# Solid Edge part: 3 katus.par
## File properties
Author: Henri
Template: Normal.par
Last saved by: Henri
Revision: 24
Application: Solid Edge
Accuracy: 0,990
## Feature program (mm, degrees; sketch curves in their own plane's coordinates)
sketch for "unnamed Protrusion 1" plane through (0, 0, 0) normal (0, 0, 1) x-axis (1, 0, 0)
  line (-137.5, -225) -> (-137.5, 225)
  line (-137.5, 225) -> (137.5, 225)
  line (137.5, 225) -> (137.5, -225)
  line (137.5, -225) -> (-137.5, -225)
extrude "unnamed Protrusion 1" add finite 5 along -normal
sketch for "ExtrudedProtrusion_4" plane through (0, 0, 0) normal (0, 0, 1) x-axis (1, 0, 0)
  line (137.5, -230) -> (-207.5, -230)
  line (-212.5, -225) -> (-207.5, -230)
  line (-212.5, 225) -> (-212.5, -225)
  line (-207.5, 230) -> (-212.5, 225)
  line (-207.5, 230) -> (137.5, 230)
  line (142.5, 225) -> (137.5, 230)
  line (142.5, 225) -> (142.5, -225)
  line (137.5, -230) -> (142.5, -225)
extrude "ExtrudedProtrusion_4" add finite 5 along +normal
chamfer "Chamfer_4" setback 5
sketch for "ExtrudedProtrusion_42" plane through (-35, 0, 5) normal (0, 0, 1) x-axis (0, 1, 0)
  circle centre (-220, 167.5) radius 1.25
extrude "ExtrudedProtrusion_42" add finite 40 along +normal
sketch for "ExtrudedProtrusion_43" plane through (-35, 0, 5) normal (0, 0, 1) x-axis (0, 1, 0)
  circle centre (220, 167.5) radius 1.25
extrude "ExtrudedProtrusion_43" add finite 40 along +normal
sketch for "ExtrudedProtrusion_44" plane through (-35, 0, 5) normal (0, 0, 1) x-axis (0, 1, 0)
  circle centre (-220, -167.5) radius 1.25
extrude "ExtrudedProtrusion_44" add finite 40 along +normal
pattern "Pattern_9" of "ExtrudedProtrusion_42" along a curve  XDirCount = 5; XDirSpacing = 55 mm
extrude "unnamed Protrusion 2" add finite 40
extrude "unnamed Protrusion 3" add finite 40
extrude "unnamed Protrusion 4" add finite 40
extrude "unnamed Protrusion 5" add finite 40
extrude "unnamed Protrusion 6" add finite 40
extrude "unnamed Protrusion 7" add finite 40
extrude "unnamed Protrusion 8" add finite 40
pattern "Pattern_12" of "ExtrudedProtrusion_43" along a curve  XDirCount = 6; XDirSpacing = 67 mm
extrude "unnamed Protrusion 9" add finite 40
extrude "unnamed Protrusion 10" add finite 40
extrude "unnamed Protrusion 11" add finite 40
extrude "unnamed Protrusion 12" add finite 40
extrude "unnamed Protrusion 13" add finite 40
pattern "Pattern_13" of "ExtrudedProtrusion_44" along a curve  XDirCount = 6; XDirSpacing = 55 mm
extrude "unnamed Protrusion 14" add finite 40
extrude "unnamed Protrusion 15" add finite 40
extrude "unnamed Protrusion 16" add finite 40
extrude "unnamed Protrusion 17" add finite 40
extrude "unnamed Protrusion 18" add finite 40
extrude "unnamed Protrusion 19" add finite 40
extrude "unnamed Protrusion 20" add finite 40
pattern "Pattern_14" of "ExtrudedProtrusion_42" along a curve  XDirCount = 5; XDirSpacing = 67 mm
extrude "unnamed Protrusion 21" add finite 40
extrude "unnamed Protrusion 22" add finite 40
extrude "unnamed Protrusion 23" add finite 40
extrude "unnamed Protrusion 24" add finite 40
swept protrusion "unnamed SweptProtrusion 1"
fillet "Round_7" radius 1
sketch used by "unnamed Cutout 1" plane through (-35, 0, 5) normal (0, 0, 1) x-axis (0, 1, 0)
extrude "unnamed Cutout 1" cut through along -normal
sketch used by "ExtrudedProtrusion_76" plane through (-35, 0, 5) normal (0, 0, 1) x-axis (0, 1, 0)
extrude "ExtrudedProtrusion_76" add finite 30 along +normal
fillet "Round_14" radius 1.5
fillet "Round_15" radius 0.5
fillet "Round_16" radius 1
sketch for "ExtrudedCutout_2" #1 plane through (-35, 0, 5) normal (0, 0, 1) x-axis (0, 1, 0)
  line (170, -102.5) -> (205, -102.5)
  line (205, -102.5) -> (205, -105)
  line (205, -105) -> (170, -105)
  line (170, -105) -> (170, -102.5)
sketch for "ExtrudedCutout_2" #2 plane through (-35, 0, 5) normal (0, 0, 1) x-axis (0, 1, 0)
  line (205, -150) -> (170, -150)
  line (170, -152.5) -> (170, -150)
  line (205, -152.5) -> (170, -152.5)
  line (205, -150) -> (205, -152.5)
extrude "ExtrudedCutout_2" cut finite 2.5 along -normal
swept protrusion "unnamed SweptProtrusion 2"
sketch for "unnamed Protrusion 25" #1 plane through (-157.5, -70, 1.75) normal (-1, 0, 0) x-axis (0, -1, 0)
  circle centre (-20.4883, -31.75) radius 1
sketch for "unnamed Protrusion 25" #2 plane through (-157.5, -70, 1.75) normal (-1, 0, 0) x-axis (0, -1, 0)
  circle centre (-20.5, -66.75) radius 1
extrude "unnamed Protrusion 25" add through along +normal
mirror "unnamed Mirror 1" of "unnamed SweptProtrusion 2", "unnamed Protrusion 25" about plane through (-171.75, -70, 3.25) normal (0, -1, 0)
swept protrusion "unnamed SweptProtrusion 3"
extrude "unnamed Protrusion 26" add through
sketch for "ExtrudedProtrusion_79" #1 plane through (-171.75, -70, 3.25) normal (0, -1, 0) x-axis (1, 0, 0)
  circle centre (6.75, -3.25) radius 1
sketch for "ExtrudedProtrusion_79" #2 plane through (-171.75, -70, 3.25) normal (0, -1, 0) x-axis (1, 0, 0)
  circle centre (6.75, -18.25) radius 1
sketch for "ExtrudedProtrusion_79" #3 plane through (-171.75, -70, 3.25) normal (0, -1, 0) x-axis (1, 0, 0)
  circle centre (6.75, -33.25) radius 1
sketch for "ExtrudedProtrusion_79" #4 plane through (-171.75, -70, 3.25) normal (0, -1, 0) x-axis (1, 0, 0)
  circle centre (6.75, -48.25) radius 1
sketch for "ExtrudedProtrusion_79" #5 plane through (-171.75, -70, 3.25) normal (0, -1, 0) x-axis (1, 0, 0)
  circle centre (6.75, -63.25) radius 1
sketch for "ExtrudedProtrusion_79" #6 plane through (-171.75, -70, 3.25) normal (0, -1, 0) x-axis (1, 0, 0)
  circle centre (6.75, -78.25) radius 1
extrude "ExtrudedProtrusion_79" add finite 40 symmetric
sketch used by "ExtrudedCutout_3" plane through (-35, 0, 5) normal (0, 0, 1) x-axis (0, 1, 0)
extrude "ExtrudedCutout_3" cut finite 0.5 along -normal
sketch for "ExtrudedCutout_4" #1 plane through (-35, 0, 5) normal (0, 0, 1) x-axis (0, 1, 0)
  circle centre (-139.149, 30.3947) radius 1.75
sketch for "ExtrudedCutout_4" #2 plane through (-35, 0, 5) normal (0, 0, 1) x-axis (0, 1, 0)
  circle centre (-179.149, 30.3947) radius 1.75
sketch for "ExtrudedCutout_4" #3 plane through (-35, 0, 5) normal (0, 0, 1) x-axis (0, 1, 0)
  circle centre (-139.149, -59.6053) radius 1.75
sketch for "ExtrudedCutout_4" #4 plane through (-35, 0, 5) normal (0, 0, 1) x-axis (0, 1, 0)
  circle centre (-179.149, -59.6053) radius 1.75
extrude "ExtrudedCutout_4" cut finite 2.5 along -normal
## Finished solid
Body 1: solid body, 212 faces, 361 edges, 126 vertices.
  Faces by surface: cylinder 91, plane 79, torus 40, spline 2
  Edges by curve: circle 156, line 131, intersection 72, ellipse 2
Bounding box of the edges (mm; curved faces can reach further): 355.000 x 460.000 x 135.000, from (-212.5, -230, -90) to (142.5, 230, 45).
Cylindrical faces by radius (mm): R0.5 x13, R0.75 x26, R1 x12, R1.25 x26, R1.5 x4, R1.75 x4, R10 x2, R10.5 x2, R12 x2
Toroidal faces (ring radius, tube radius in mm): R0.25 r1 x26, R0.5 r0.5 x4, R1 r0.5 x2, R11 r0.5 x2, R11.5 r0.5 x2, R11.5 r1.5 x2, R12.5 r0.5 x2
Planar faces by outward normal: +x 12, +y 7, +z 35, -x 6, -y 7, -z 4, oblique 8
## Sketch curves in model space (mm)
line (117.5, 75, 5) -> (35, 75, 5)
line (35, 75, 5) -> (35, 125, 5)
line (35, 125, 5) -> (117.5, 125, 5)
line (117.5, 125, 5) -> (117.5, 75, 5)
circle centre (24.6053, -139.149, 5) radius 1.75
circle centre (24.6053, -179.149, 5) radius 1.75
circle centre (-65.3947, -139.149, 5) radius 1.75
circle centre (-65.3947, -179.149, 5) radius 1.75
line (24.6053, -139.149, 5) -> (-65.3947, -139.149, 5)
line (-65.3947, -139.149, 5) -> (-65.3947, -179.149, 5)
line (-65.3947, -179.149, 5) -> (24.6053, -179.149, 5)
line (24.6053, -179.149, 5) -> (24.6053, -139.149, 5)
circle centre (-165, -70, -45) radius 1
circle centre (-165, -70, -75) radius 1
circle centre (-165, -70, -60) radius 1
circle centre (-165, -70, 0) radius 1
circle centre (-165, -70, -30) radius 1
circle centre (-165, -70, -15) radius 1
line (-165, -70, 2.7991) -> (-165, -70, -93.6141)
line (-172.5872, -70, -75) -> (-152.3416, -70, -75)
line (-171.3527, -70, -60) -> (-151.4775, -70, -60)
line (-173.4513, -70, -45) -> (-150.1196, -70, -45)
line (-173.4513, -70, -30) -> (-152.3416, -70, -30)
line (-171.3527, -70, -15) -> (-152.3416, -70, -15)
line (-171.3527, -70, 0) -> (-153.3292, -70, 0)
line (-157.5, -49.5, -6.1655) -> (-157.5, -49.5, -123.3075)
line (-150, -49.5, 35) -> (-150, -49.5, 5)
arc centre (-157.5, -49.5, 35) radius 7.5 from (-165, -49.5, 35) through (-157.2778, -49.5, 42.4967) to (-150, -49.5, 35)
line (-165, -49.5, -90) -> (-165, -49.5, 35)
circle centre (-150, -49.5, 5) radius 1.25
line (-286.3169, -25, 5) -> (-37.1535, -25, 5)
line (-292.5116, 25, 5) -> (-57.8024, 25, 5)
line (-157.5, -45, 5) -> (-157.5, -95, 5)
line (-187.5, -95, 5) -> (-157.5, -95, 5)
arc centre (-187.5, -85, 5) radius 10 from (-197.5, -85, 5) through (-194.3624, -92.2737, 5) to (-187.5, -95, 5)
line (-197.5, -55, 5) -> (-197.5, -85, 5)
arc centre (-187.5, -55, 5) radius 10 from (-197.5, -55, 5) through (-194.3624, -47.7263, 5) to (-187.5, -45, 5)
line (-187.5, -45, 5) -> (-157.5, -45, 5)
line (-202.5, -220, 57.5) -> (-202.5, 220, 57.5)
line (-202.5, 220, 57.5) -> (132.5, 220, 57.5)
line (132.5, 220, 57.5) -> (132.5, -220, 57.5)
line (132.5, -220, 57.5) -> (-202.5, -220, 57.5)
circle centre (0, -220, 42.5) radius 0.75
line (0, -220, 60.8189) -> (0, -220, 54.5864)
line (0, -222.3261, 42.5) -> (0, -216.8481, 42.5)
line (-159, -45, 5) -> (-159, -44.5, 5)
line (-159, -44.5, 5) -> (-187.5, -44.5, 5)
arc centre (-187.5, -55, 5) radius 10.5 from (-187.5, -44.5, 5) through (-195.1374, -47.7945, 5) to (-198, -55, 5)
line (-198, -55, 5) -> (-198, -85, 5)
arc centre (-187.5, -85, 5) radius 10.5 from (-198, -85, 5) through (-194.7055, -92.6374, 5) to (-187.5, -95.5, 5)
line (-187.5, -95.5, 5) -> (-159, -95.5, 5)
line (-159, -97, 5) -> (-159, -95.5, 5)
line (-159, -44.5, 5) -> (-159, -43, 5)
line (-187.5, -43, 5) -> (-159, -43, 5)
arc centre (-187.5, -55, 5) radius 12 from (-199.5, -55, 5) through (-195.7349, -46.2715, 5) to (-187.5, -43, 5)
line (-199.5, -55, 5) -> (-199.5, -85, 5)
arc centre (-187.5, -85, 5) radius 12 from (-199.5, -85, 5) through (-195.7349, -93.7285, 5) to (-187.5, -97, 5)
line (-187.5, -97, 5) -> (-159, -97, 5)
circle centre (132.5, 220, 5) radius 1.25
circle centre (-202.5, 220, 5) radius 1.25
circle centre (132.5, -220, 5) radius 1.25
circle centre (-202.5, -220, 5) radius 1.25
line (-202.5, 220, 5) -> (132.5, 220, 5)
line (132.5, 220, 5) -> (132.5, -220, 5)
line (132.5, -220, 5) -> (-202.5, -220, 5)
line (-202.5, -220, 5) -> (-202.5, 220, 5)
line (117.5, 205, 5) -> (117.5, 170, 5)
line (117.5, 170, 5) -> (115, 170, 5)
line (115, 205, 5) -> (115, 170, 5)
line (115, 205, 5) -> (117.5, 205, 5)
line (67.5, 205, 5) -> (70, 205, 5)
line (70, 205, 5) -> (70, 170, 5)
line (70, 170, 5) -> (67.5, 170, 5)
line (67.5, 170, 5) -> (67.5, 205, 5)
circle centre (-157.5, -49.5, -65) radius 1
circle centre (-157.5, -49.5117, -30) radius 1
line (137.5, 225, 0) -> (137.5, -225, 0)
line (137.5, -225, 0) -> (-137.5, -225, 0)
line (-137.5, -225, 0) -> (-137.5, 225, 0)
line (-137.5, 225, 0) -> (137.5, 225, 0)
line (142.5, 225, 0) -> (137.5, 230, 0)
line (142.5, 225, 0) -> (142.5, -225, 0)
line (137.5, -230, 0) -> (142.5, -225, 0)
line (137.5, -230, 0) -> (-207.5, -230, 0)
line (-212.5, -225, 0) -> (-207.5, -230, 0)
line (-212.5, 225, 0) -> (-212.5, -225, 0)
line (-207.5, 230, 0) -> (-212.5, 225, 0)
line (-207.5, 230, 0) -> (137.5, 230, 0)
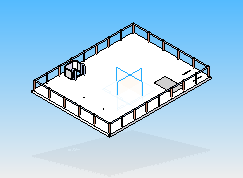
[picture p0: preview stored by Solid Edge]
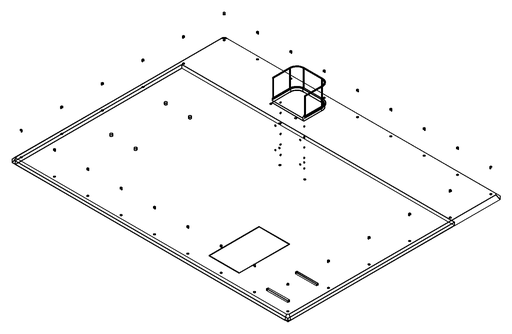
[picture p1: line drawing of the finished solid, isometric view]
